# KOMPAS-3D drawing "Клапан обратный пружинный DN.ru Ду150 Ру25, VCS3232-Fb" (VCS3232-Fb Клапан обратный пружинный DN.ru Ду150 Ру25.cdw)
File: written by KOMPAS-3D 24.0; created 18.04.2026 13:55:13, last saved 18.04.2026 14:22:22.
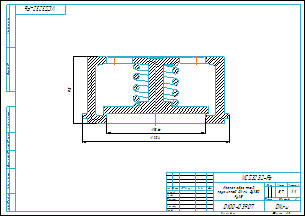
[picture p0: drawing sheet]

Document properties: c3d_UniqueCompID: 071bd168-1a06-425c-849c-e99e84a96128; Наименование: Деталь; Автор: 712; Класс точности: c; Знак неуказанной шероховатости: Шероховатость не задана; Рассекать на разрезах: Да; c3d_UniqueCompID: 071bd168-1a06-425c-849c-e99e84a96128; Наименование: Деталь; Автор: 712; Класс точности: c; Знак неуказанной шероховатости: Шероховатость не задана; Рассекать на разрезах: Да; c3d_UniqueCompID: 071bd168-1a06-425c-849c-e99e84a96128; Наименование: Деталь; Автор: 712; Класс точности: c; Знак неуказанной шероховатости: Шероховатость не задана; Рассекать на разрезах: Да; c3d_UniqueCompID: 071bd168-1a06-425c-849c-e99e84a96128; Наименование: Деталь; Автор: 712; Класс точности: c; Знак неуказанной шероховатости: Шероховатость не задана; Рассекать на разрезах: Да; c3d_UniqueCompID: 071bd168-1a06-425c-849c-e99e84a96128; Наименование: Деталь; Автор: 712; Класс точности: c; Знак неуказанной шероховатости: Шероховатость не задана; Рассекать на разрезах: Да; c3d_UniqueCompID: 071bd168-1a06-425c-849c-e99e84a96128; Наименование: Деталь; Автор: 712; Класс точности: c; Знак неуказанной шероховатости: Шероховатость не задана; Рассекать на разрезах: Да; c3d_UniqueCompID: 071bd168-1a06-425c-849c-e99e84a96128; Наименование: Деталь; Автор: 712; Класс точности: c; Знак неуказанной шероховатости: Шероховатость не задана; Рассекать на разрезах: Да; c3d_UniqueCompID: 071bd168-1a06-425c-849c-e99e84a96128; Наименование: Деталь; Автор: 712; Класс точности: c; Знак неуказанной шероховатости: Шероховатость не задана; Рассекать на разрезах: Да; c3d_UniqueCompID: 071bd168-1a06-425c-849c-e99e84a96128; Наименование: Деталь; Автор: 712; Класс точности: c; Знак неуказанной шероховатости: Шероховатость не задана; Рассекать на разрезах: Да; c3d_UniqueCompID: 071bd168-1a06-425c-849c-e99e84a96128; Наименование: Деталь; Автор: 712; Класс точности: c; Знак неуказанной шероховатости: Шероховатость не задана; Рассекать на разрезах: Да; c3d_UniqueCompID: 071bd168-1a06-425c-849c-e99e84a96128; Наименование: Деталь; Автор: 712; Класс точности: c; Знак неуказанной шероховатости: Шероховатость не задана; Рассекать на разрезах: Да; Автор: 712; Форматы листов документа: A3; Полное имя файла: VCS3232-Fb Клапан обратный пружинный DN.ru Ду150 Ру25.m3d; Масса: 5.7; Наименование: Клапан обратный пружинный DN.ru Ду150 Ру25; Количество листов документа: 1; Примечание: D100-03907

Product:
- Component: Пружина 1086-1091 ГОСТ 18793-80  | qty 1  | additional columns: 3953604318-4147491677-0; Деталь; Пользователь Windows; c; Шероховатость не задана; Да; Сталь 10  ГОСТ 1050-88; source file: Деталь_2.m3d
- Body: Тело 1  | qty 1
    Масса: 8.55169
- Part/product: Клапан обратный пружинный DN.ru Ду150 Ру25  | designation VCS3232-Fb
    Масса: 5.7
    Раздел спецификации: Прочие изделия
    Примечание: D100-03907
    additional columns: 071bd168-1a06-425c-849c-e99e84a96128; Деталь; 712; c; Шероховатость не задана; Да

Views: Вид 1, Местный разрез 1, Спереди
Referenced files in C:\Users\712\Desktop\Новая папка (4)\: VCS3232-Fb Клапан обратный пружинный DN.ru Ду15 Ру40.m3d, VCS3232-Fb Клапан обратный пружинный DN.ru Ду150 Ру25.m3d, VCS3232-Fb Клапан обратный пружинный DN.ru Ду15 Ру40.cdw
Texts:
  VCS3232-Fb
  Клапан обратный
  пружинный DN.ru Ду150
  Ру25
  Клапан обратный пружинный DN.ru Ду150 Ру25
  VCS3232-Fb Клапан обратный пружинный DN.ru Ду150 Ру25
Dimensions and other numbers on the sheet: 0; 3; 2; 4; 204; 136; 93; 1:1; 1; 5,7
